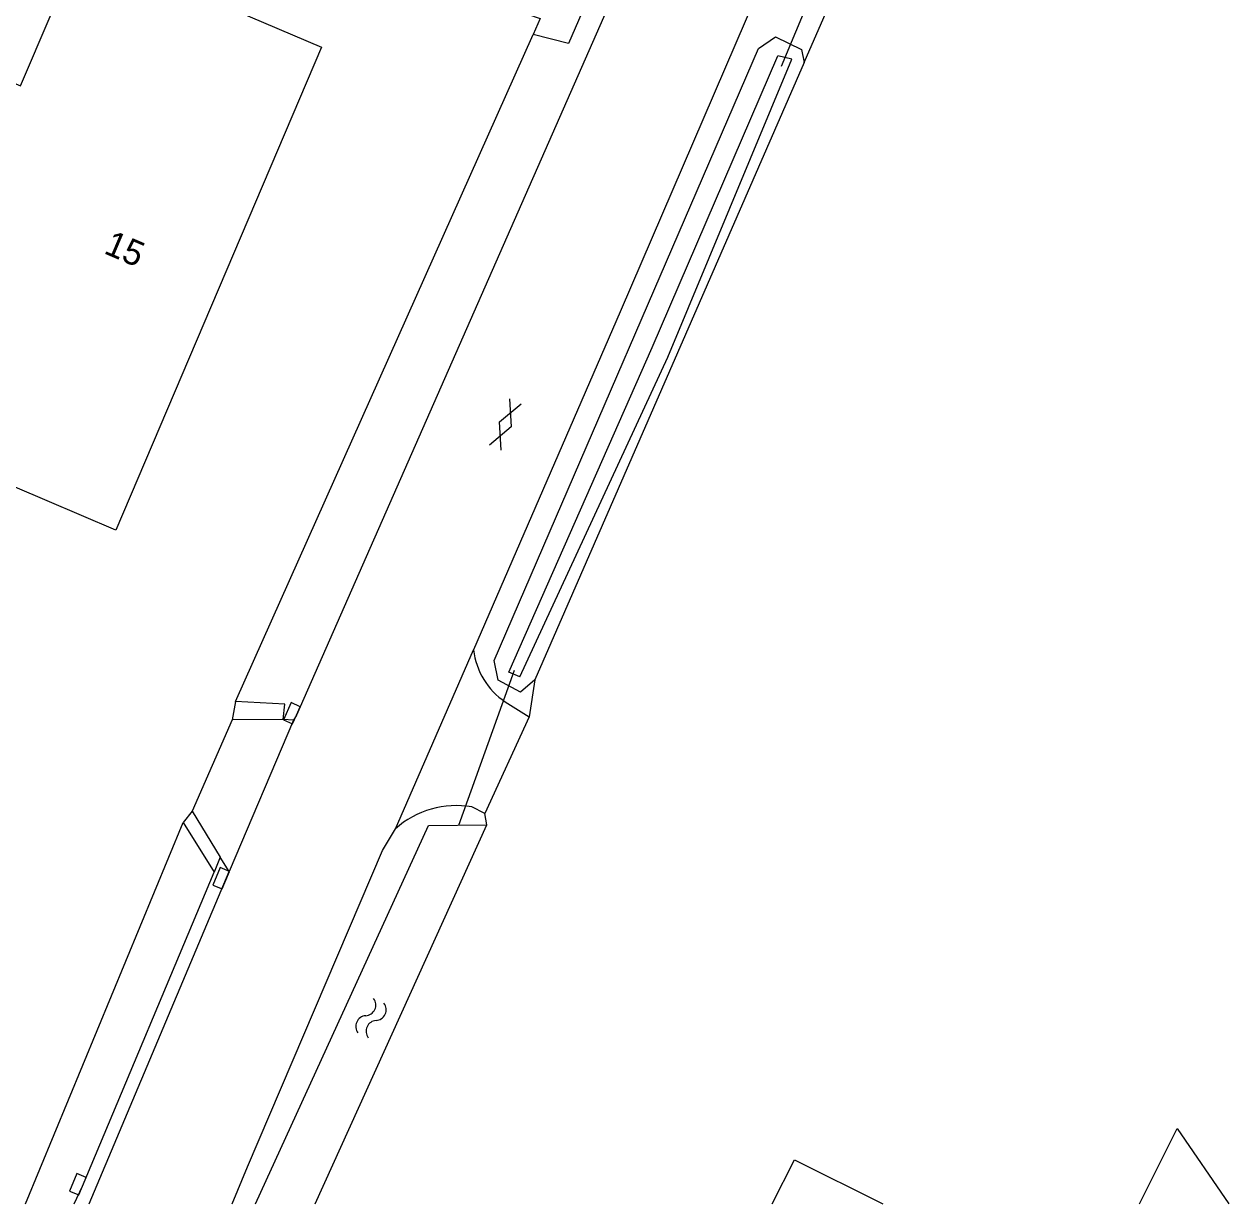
# Model space of a CAD drawing. Extents: x 133000 to 136000, y 400500 to 403500.
# Drawn here: x 134476.69 to 134524.39, y 400500 to 400546.71 of the extents above; entities that cross this region are included whole.
import ezdxf

# ---------------------------------------------------------------- set-up
doc = ezdxf.new("R2010")
doc.units = 0
for name, color, linetype in [('gg-afsc-lijn draadraster', 7, 'Continuous'), ('gg-anno-huisnummerreeks BGT', 7, 'Continuous'), ('gg-bbg-gedigitaliseerde bebouwing', 7, 'Continuous'), ('gg-bbg-hoofdgebouw', 7, 'Continuous'), ('gg-knt-bronhoudergrens', 7, 'Continuous'), ('gg-knt-verharding', 7, 'Continuous'), ('gg-knt-verharding nz', 7, 'Continuous'), ('gg-kntw-bovenkant insteek waterloop', 7, 'Continuous'), ('gg-kntw-waterlijn', 7, 'Continuous'), ('gg-kwrk-duiker nz buis', 7, 'Continuous'), ('gt-grn-groengrens', 7, 'Continuous'), ('gt-grn-groengrens NZ', 7, 'Continuous'), ('gt-grn-vlakafsluiter', 7, 'Continuous'), ('gt-symb-gesloten verharding', 7, 'Continuous'), ('gt-symb-kolk', 7, 'Continuous'), ('gt-symb-watersymbool', 7, 'Continuous')]:
    doc.layers.add(name, color=color, linetype=linetype)

# ---------------------------------------------------------------- blocks, each defined once
blk = doc.blocks.new('gt0-GESVH1')
at = {"layer": 'gt-symb-gesloten verharding'}
for p, q in [((-0.992, -0.261), (0.008, 0.239)), ((0.008, -0.261), (-0.992, 0.239)), ((0.008, 0.239), (1.008, -0.261)), ((1.008, 0.239), (0.008, -0.261))]:
    blk.add_line(p, q, dxfattribs=at)
blk = doc.blocks.new('gt0-KOLK')
at = {"layer": 'gt-symb-kolk'}
blk.add_lwpolyline([(0, 0), (0.375, 0), (0.375, 0.4), (-0.375, 0.4), (-0.375, 0), (0, 0)], dxfattribs=at)
blk = doc.blocks.new('gt0-WA')
at = {"layer": 'gt-symb-watersymbool'}
for centre, start, end in [((-0.323, 0.022), 28.0725, 151.9275), ((0.427, 0.422), 208.0725, 331.9275), ((-0.323, -0.428), 28.0725, 151.9275), ((0.427, -0.028), 208.0725, 331.9275)]:
    blk.add_arc(centre, 0.425, start, end, dxfattribs=at)

msp = doc.modelspace()

# ---------------------------------------------------------------- linework, layer by layer
at = {"layer": 'gg-afsc-lijn draadraster'}
msp.add_lwpolyline([(134520.848, 400500), (134522.346, 400502.983), (134524.39, 400500)], dxfattribs=at)
at = {"layer": 'gg-bbg-gedigitaliseerde bebouwing'}
msp.add_line((134507.188, 400501.746), (134510.683, 400500), dxfattribs=at)
at = {"layer": 'gg-bbg-hoofdgebouw'}
msp.add_line((134506.311, 400500), (134507.188, 400501.746), dxfattribs=at)
msp.add_lwpolyline([(134468.947, 400547.51), (134476.546, 400544.27), (134478.931, 400549.867), (134483.87, 400547.771), (134488.47, 400545.801), (134480.32, 400526.681), (134470.799, 400530.74), (134471.513, 400532.414)], dxfattribs=at)
at = {"layer": 'gg-knt-bronhoudergrens'}
msp.add_lwpolyline([(134520.848, 400500), (134522.346, 400502.983), (134524.39, 400500)], dxfattribs=at)
at = {"layer": 'gg-knt-verharding'}
for p, q in [((134495.741, 400519.883), (134496.686, 400519.279)), ((134496.686, 400519.279), (134494.936, 400515.459)), ((134487.352, 400519.151), (134484.815, 400513.156)), ((134486.942, 400519.181), (134484.931, 400519.162)), ((134487.352, 400519.151), (134486.942, 400519.181)), ((134483.341, 400515.554), (134484.459, 400513.725)), ((134494.936, 400515.459), (134494.416, 400515.717)), ((134484.459, 400513.725), (134484.218, 400513.139)), ((134484.815, 400513.156), (134484.459, 400513.725)), ((134479.262, 400500), (134484.815, 400513.156))]:
    msp.add_line(p, q, dxfattribs=at)
for points in [[(134515.343, 400570.314), (134514.31, 400568.109), (134511.455, 400561.27), (134500.289, 400535.315), (134494.483, 400521.932)], [(134499.919, 400547.641), (134487.473, 400519.345), (134487.352, 400519.151)], [(134484.924, 400500), (134485.534, 400501.473), (134490.884, 400513.999), (134491.396, 400514.857)], [(134478.669, 400500), (134479.008, 400500.699), (134484.218, 400513.139)]]:
    msp.add_lwpolyline(points, dxfattribs=at)
for centre, radius, start, end in [((134497.319, 400522.263), 2.856, 186.6504, 236.4459), ((134493.798, 400512.153), 3.617, 80.1699, 131.6207)]:
    msp.add_arc(centre, radius, start, end, dxfattribs=at)
at = {"layer": 'gg-knt-verharding nz'}
msp.add_line((134491.396, 400514.857), (134494.483, 400521.932), dxfattribs=at)
at = {"layer": 'gg-kntw-bovenkant insteek waterloop'}
for p, q in [((134507.573, 400545.196), (134496.917, 400520.752)), ((134485.845, 400500), (134492.697, 400514.986)), ((134488.213, 400500), (134495.016, 400515.009)), ((134492.697, 400514.986), (134495.016, 400515.009))]:
    msp.add_line(p, q, dxfattribs=at)
for points in [[(134401.018, 400525.34), (134394.271, 400551.314), (134386.622, 400579.152), (134383.859, 400586.057), (134440.296, 400566.357), (134497.127, 400546.941), (134496.85, 400546.301)], [(134499.073, 400547.876), (134498.238, 400545.945), (134496.85, 400546.301)], [(134505.765, 400545.754), (134506.437, 400546.209), (134507.462, 400545.703), (134507.573, 400545.196)], [(134496.917, 400520.752), (134496.342, 400520.264), (134495.454, 400520.741), (134495.295, 400521.519), (134505.765, 400545.754)]]:
    msp.add_lwpolyline(points, dxfattribs=at)
at = {"layer": 'gg-kntw-waterlijn'}
for points in [[(134496.312, 400520.874), (134495.888, 400521.05), (134501.562, 400533.909), (134506.525, 400545.461)], [(134496.312, 400520.874), (134502.174, 400533.528), (134507.086, 400545.321), (134506.525, 400545.461)]]:
    msp.add_lwpolyline(points, dxfattribs=at)
at = {"layer": 'gg-kwrk-duiker nz buis'}
for p, q in [((134506.671, 400545.051), (134507.982, 400548.17)), ((134493.905, 400514.996), (134496.106, 400521.136))]:
    msp.add_line(p, q, dxfattribs=at)
at = {"layer": 'gt-grn-groengrens'}
for p, q in [((134496.917, 400520.752), (134496.686, 400519.279)), ((134485.058, 400519.893), (134484.931, 400519.162)), ((134483.341, 400515.554), (134482.993, 400515.102)), ((134495.016, 400515.009), (134494.936, 400515.459)), ((134476.739, 400500), (134482.993, 400515.102)), ((134482.993, 400515.102), (134484.218, 400513.139))]:
    msp.add_line(p, q, dxfattribs=at)
msp.add_lwpolyline([(134486.942, 400519.181), (134487.013, 400519.792), (134485.058, 400519.893)], dxfattribs=at)
at = {"layer": 'gt-grn-groengrens NZ'}
msp.add_line((134507.573, 400545.196), (134508.533, 400547.399), dxfattribs=at)
at = {"layer": 'gt-grn-vlakafsluiter'}
for p, q in [((134485.058, 400519.893), (134496.85, 400546.301)), ((134484.931, 400519.162), (134483.341, 400515.554))]:
    msp.add_line(p, q, dxfattribs=at)

# ---------------------------------------------------------------- block references
at = {"layer": 'gt-symb-gesloten verharding', "rotation": 66.74124066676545}
msp.add_blockref('gt0-GESVH1', (134495.729, 400530.859), dxfattribs=at)
at = {"layer": 'gt-symb-kolk'}
for p, rotation in [((134487.473, 400519.345), 66.09568596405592), ((134484.673, 400512.816), 67.3863427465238), ((134479.008, 400500.699), 67.27398934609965)]:
    msp.add_blockref('gt0-KOLK', p, dxfattribs=dict(at, rotation=rotation))
at = {"layer": 'gt-symb-watersymbool', "rotation": 65.4089995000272}
msp.add_blockref('gt0-WA', (134490.398, 400507.31), dxfattribs=at)

# ---------------------------------------------------------------- texts
at = {"layer": 'gg-anno-huisnummerreeks BGT'}
msp.add_text('15', height=1, rotation=336.9, dxfattribs=at).set_placement((134479.805, 400537.655))

doc.saveas('drawing.dxf')
